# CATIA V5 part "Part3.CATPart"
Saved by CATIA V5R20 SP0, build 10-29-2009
Part number: Part3
Bounding box of the stored display mesh (mm): x 0 to 7.5, y -4 to 4, z -3.991 to 60.991
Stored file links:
  E:\Ehsan\Amoozesh\CATIA\CATIA Course\Basic\Exercises\Assembly\1\Part3.CATPart
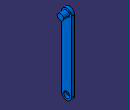
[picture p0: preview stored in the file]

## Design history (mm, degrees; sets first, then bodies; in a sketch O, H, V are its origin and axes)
Body1 (main body)
  Sketch1 on yz-plane, origin (0, 0, 0), H (0, 1, 0), V (0, 0, 1)
    construction line L1 (0, 0) -> (0, 57)
    line L2 (-4, 0) -> (-4, 57)
    line L3 (4, 57) -> (4, 0)
    arc A1 centre (0, 57) radius 4 from (-4, 57) to (4, 57) cw
    arc A2 centre (0, 0) radius 4 from (4, 0) to (-4, 0) cw
    length L1 = 57
    distance L1 L2 = 4
    vertical: L1 V
    tangency: A1 L2, A2 L2, A1 L3, A2 L3
  Pad1: profile Sketch1, direction (1, 0, 0), length 2.5
  Sketch2 on end face of Pad1, origin (2.5, 0, 0), H (0, 1, 0), V (0, 0, 1)
    circle A1 centre (0, 0) radius 2.5
    radius A1 = 2.5
  Pocket1: profile Sketch2, direction (-1, 0, 0), through (limit type 3)
  Sketch3 on end face of Pad1, origin (2.5, 0, 0), H (0, 1, 0), V (0, 0, 1)
    circle A1 centre (0, 57) radius 2.5
    reference projected arc E1 centre (0, 57) radius 4 from (4, 57) to (-4, 57) ccw from edge [face of Pad1 from Sketch1.A1 | end face of Pad1]
    radius A1 = 2.5
    concentricity: A1 E1
  Pad2: profile Sketch3, direction (1, 0, 0), length 5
